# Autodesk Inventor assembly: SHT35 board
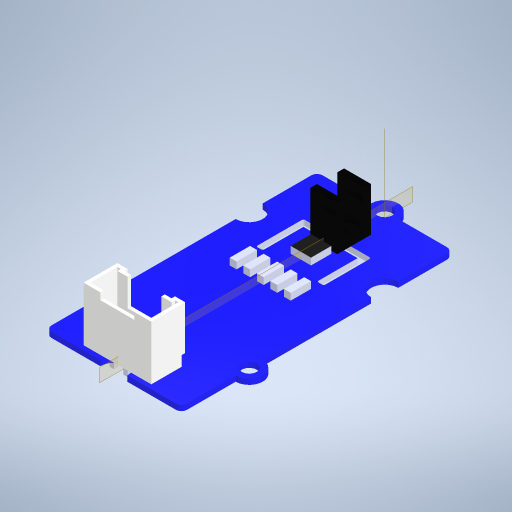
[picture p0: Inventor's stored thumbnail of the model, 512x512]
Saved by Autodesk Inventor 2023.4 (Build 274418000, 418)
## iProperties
Created: 2019-06
Part Number: SHT35 board
Document SubType Name: Assembly
Designer: mel
Author: mel
Sending System: SolidWorks 2018
Last Author: Hazel
Last Saved: 2019-08-13
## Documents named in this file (3)
- C:\Users\mel\Downloads\grove-sht35-1.snapshot.2\SHT35 board\SHT35 board.iam
- C:\Users\mel\Downloads\grove-sht35-1.snapshot.2\SHT35 board\Grove socket.ipt
- C:\Users\mel\Downloads\grove-sht35-1.snapshot.2\SHT35 board\SHT31 sensor board.ipt
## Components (2 placed, 2 different names)
1. Grove socket:1
2. SHT31 sensor board:2
